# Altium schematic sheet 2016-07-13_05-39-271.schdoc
size 327 x 144 mm; SheetNumber: 1; SheetTotal: 1
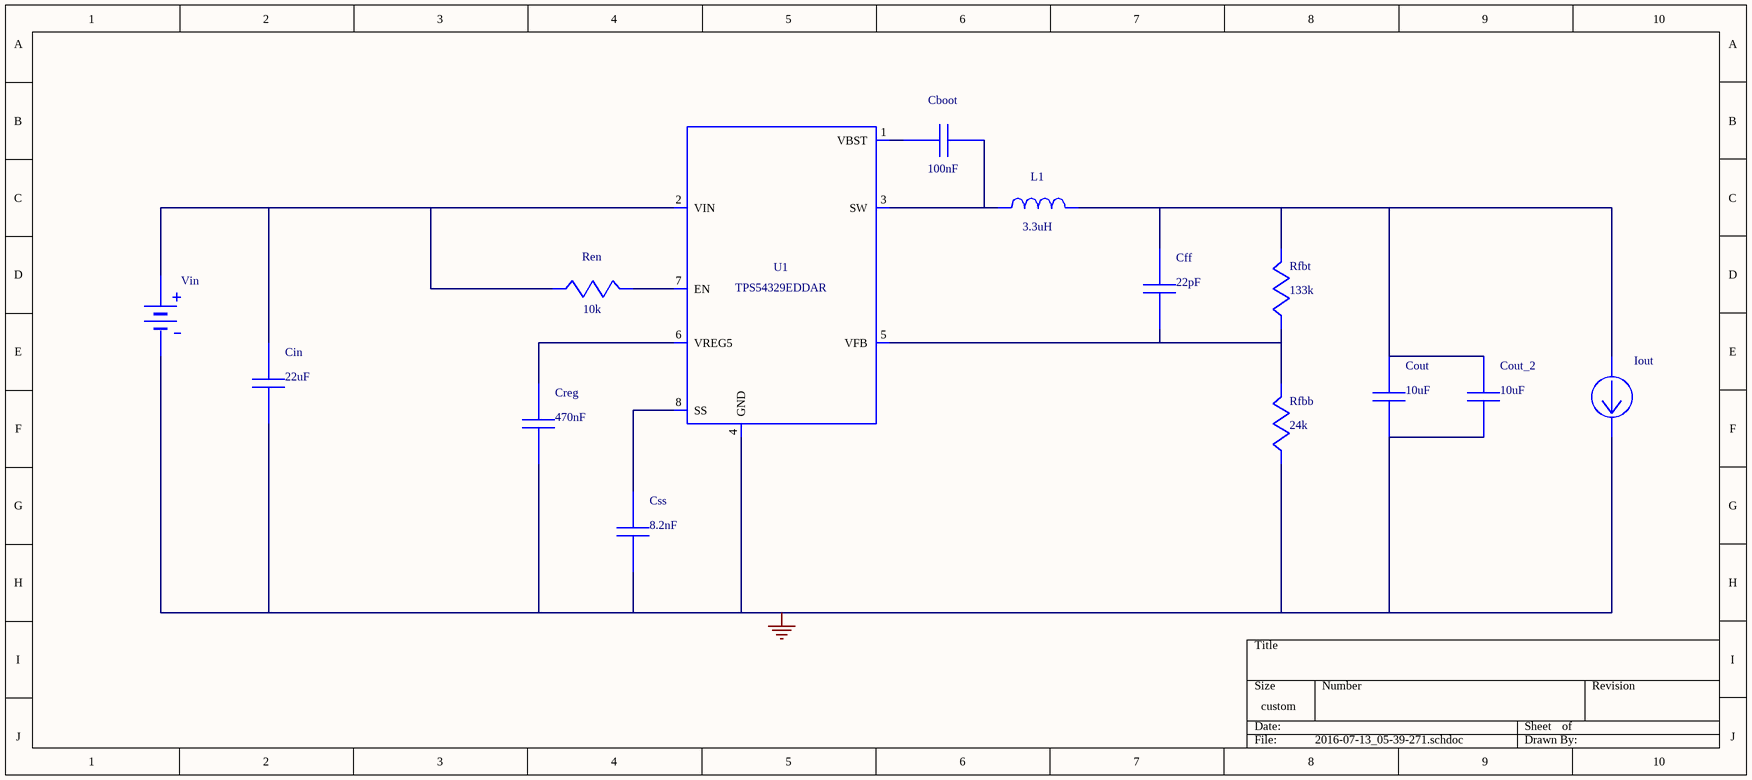
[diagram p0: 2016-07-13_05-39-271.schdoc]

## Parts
Cboot  value 100nF  (hidden comment: GRM155R61A104KA01D)
Cff  value 22pF  (hidden comment: C0805C220K3GACTU)
Cin  value 22uF  (hidden comment: GRM32ER61E226KE15L)
Cout  value 10uF  (hidden comment: GRM319R61C106KE15D)
Cout_2  value 10uF  (hidden comment: GRM319R61C106KE15D)
Creg  value 470nF  (hidden comment: GRM155R61A474KE15D)
Css  value 8.2nF  (hidden comment: GRM033R61A822KA01D)
Iout  WB_CURRENT_LOAD  (value not drawn)
L1  value 3.3uH  (hidden comment: SRR6038-3R3Y)
Ren  value 10k  (hidden comment: CRCW040210K0FKED)
Rfbb  value 24k  (hidden comment: RC0603FR-0724KL)
Rfbt  value 133k  (hidden comment: CRCW0402133KFKED)
U1  TPS54229DDAR  (value not drawn)
Vin  WB_BATTERY  (value not drawn)

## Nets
0: Cin.2 Cout.2 Cout_2.2 Creg.2 Css.2 Iout.2(-) Rfbb.2 U1.4(GND) U1.9(ETPAD) Vin.2(-)
NetCboot_1: Cboot.1 U1.1(VBST)
NetCboot_2: Cboot.2 L1.2 U1.3(SW)
NetCff_1: Cff.1 Cout.1 Cout_2.1 Iout.1(+) L1.1 Rfbt.1
NetCff_2: Cff.2 Rfbb.1 Rfbt.2 U1.5(VFB)
NetCin_1: Cin.1 Ren.2 U1.2(VIN) Vin.1(+)
NetCreg_1: Creg.1 U1.6(VREG5)
NetCss_1: Css.1 U1.8(SS)
NetRen_1: Ren.1 U1.7(EN)

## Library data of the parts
Cboot = GRM155R61A104KA01D: GRM155R61A104KA0; Manufacturer Name: MuRata
Cff = C0805C220K3GACTU: Manufacturer Name: Kemet
Cin = GRM32ER61E226KE15L: GRM32ER61E226KE1; Manufacturer Name: MuRata
Cout Cout_2 = GRM319R61C106KE15D: GRM319R61C106KE1; Manufacturer Name: MuRata
Creg = GRM155R61A474KE15D: GRM155R61A474KE1; Manufacturer Name: MuRata
Css = GRM033R61A822KA01D: GRM033R61A822KA0; Manufacturer Name: MuRata
L1 = SRR6038-3R3Y: Manufacturer Name: Bourns
Ren = CRCW040210K0FKED: Manufacturer Name: Vishay-Dale
Rfbb = RC0603FR-0724KL: Manufacturer Name: Yageo America
Rfbt = CRCW0402133KFKED: Manufacturer Name: Vishay-Dale
U1 = TPS54229DDAR: TPS54329EDDAR; Manufacturer Name: Texas Instruments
